// Mitsubishi GX Works2 project: Jyuden   PLC: Q00J
// 受電設備

PROGRAM MAIN
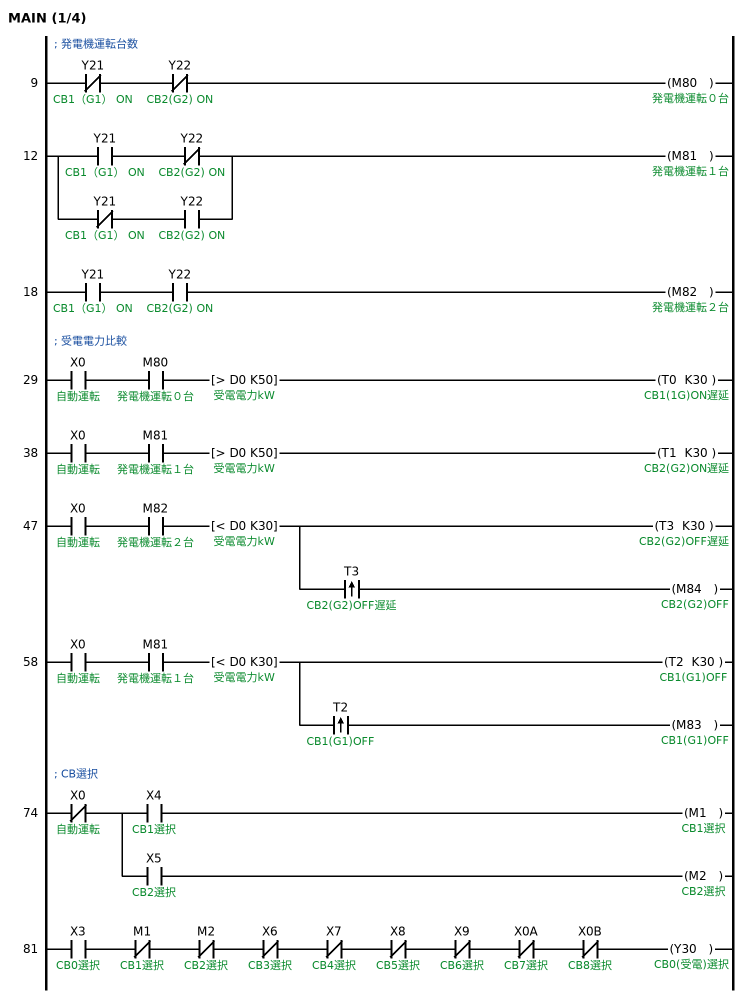
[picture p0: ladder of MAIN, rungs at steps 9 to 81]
; 発電機運転台数
9     LDI     Y21  ; CB1（G1） ON
      ANI     Y22  ; CB2(G2) ON
      OUT     M80  ; 発電機運転０台
12    LD      Y21  ; CB1（G1） ON
      ANI     Y22  ; CB2(G2) ON
      LDI     Y21  ; CB1（G1） ON
      AND     Y22  ; CB2(G2) ON
      ORB
      OUT     M81  ; 発電機運転１台
18    LD      Y21  ; CB1（G1） ON
      AND     Y22  ; CB2(G2) ON
      OUT     M82  ; 発電機運転２台
; 受電電力比較
29    LD      X0  ; 自動運転
      AND     M80  ; 発電機運転０台
      AND>    D0 K50  ; 受電電力kW
      OUT     T0 K30  ; CB1(1G)ON遅延
38    LD      X0  ; 自動運転
      AND     M81  ; 発電機運転１台
      AND>    D0 K50  ; 受電電力kW
      OUT     T1 K30  ; CB2(G2)ON遅延
47    LD      X0  ; 自動運転
      AND     M82  ; 発電機運転２台
      AND<    D0 K30  ; 受電電力kW
      OUT     T3 K30  ; CB2(G2)OFF遅延
      ANDP    T3  ; CB2(G2)OFF遅延
      OUT     M84  ; CB2(G2)OFF
58    LD      X0  ; 自動運転
      AND     M81  ; 発電機運転１台
      AND<    D0 K30  ; 受電電力kW
      OUT     T2 K30  ; CB1(G1)OFF
      ANDP    T2  ; CB1(G1)OFF
      OUT     M83  ; CB1(G1)OFF
; CB選択
74    LDI     X0  ; 自動運転
      MPS
      AND     X4  ; CB1選択
      OUT     M1  ; CB1選択
      MPP
      AND     X5  ; CB2選択
      OUT     M2  ; CB2選択
81    LD      X3  ; CB0選択
      ANI     M1  ; CB1選択
      ANI     M2  ; CB2選択
      ANI     X6  ; CB3選択
      ANI     X7  ; CB4選択
      ANI     X8  ; CB5選択
      ANI     X9  ; CB6選択
      ANI     X0A  ; CB7選択
      ANI     X0B  ; CB8選択
      OUT     Y30  ; CB0(受電)選択
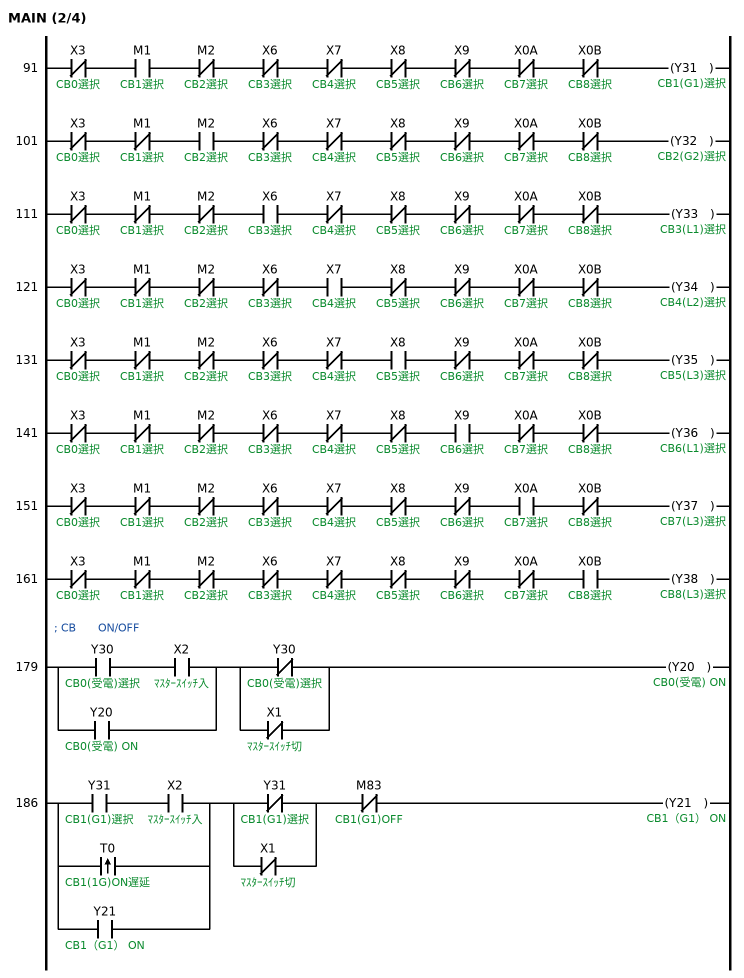
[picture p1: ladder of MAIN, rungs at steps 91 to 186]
91    LDI     X3  ; CB0選択
      AND     M1  ; CB1選択
      ANI     M2  ; CB2選択
      ANI     X6  ; CB3選択
      ANI     X7  ; CB4選択
      ANI     X8  ; CB5選択
      ANI     X9  ; CB6選択
      ANI     X0A  ; CB7選択
      ANI     X0B  ; CB8選択
      OUT     Y31  ; CB1(G1)選択
101   LDI     X3  ; CB0選択
      ANI     M1  ; CB1選択
      AND     M2  ; CB2選択
      ANI     X6  ; CB3選択
      ANI     X7  ; CB4選択
      ANI     X8  ; CB5選択
      ANI     X9  ; CB6選択
      ANI     X0A  ; CB7選択
      ANI     X0B  ; CB8選択
      OUT     Y32  ; CB2(G2)選択
111   LDI     X3  ; CB0選択
      ANI     M1  ; CB1選択
      ANI     M2  ; CB2選択
      AND     X6  ; CB3選択
      ANI     X7  ; CB4選択
      ANI     X8  ; CB5選択
      ANI     X9  ; CB6選択
      ANI     X0A  ; CB7選択
      ANI     X0B  ; CB8選択
      OUT     Y33  ; CB3(L1)選択
121   LDI     X3  ; CB0選択
      ANI     M1  ; CB1選択
      ANI     M2  ; CB2選択
      ANI     X6  ; CB3選択
      AND     X7  ; CB4選択
      ANI     X8  ; CB5選択
      ANI     X9  ; CB6選択
      ANI     X0A  ; CB7選択
      ANI     X0B  ; CB8選択
      OUT     Y34  ; CB4(L2)選択
131   LDI     X3  ; CB0選択
      ANI     M1  ; CB1選択
      ANI     M2  ; CB2選択
      ANI     X6  ; CB3選択
      ANI     X7  ; CB4選択
      AND     X8  ; CB5選択
      ANI     X9  ; CB6選択
      ANI     X0A  ; CB7選択
      ANI     X0B  ; CB8選択
      OUT     Y35  ; CB5(L3)選択
141   LDI     X3  ; CB0選択
      ANI     M1  ; CB1選択
      ANI     M2  ; CB2選択
      ANI     X6  ; CB3選択
      ANI     X7  ; CB4選択
      ANI     X8  ; CB5選択
      AND     X9  ; CB6選択
      ANI     X0A  ; CB7選択
      ANI     X0B  ; CB8選択
      OUT     Y36  ; CB6(L1)選択
151   LDI     X3  ; CB0選択
      ANI     M1  ; CB1選択
      ANI     M2  ; CB2選択
      ANI     X6  ; CB3選択
      ANI     X7  ; CB4選択
      ANI     X8  ; CB5選択
      ANI     X9  ; CB6選択
      AND     X0A  ; CB7選択
      ANI     X0B  ; CB8選択
      OUT     Y37  ; CB7(L3)選択
161   LDI     X3  ; CB0選択
      ANI     M1  ; CB1選択
      ANI     M2  ; CB2選択
      ANI     X6  ; CB3選択
      ANI     X7  ; CB4選択
      ANI     X8  ; CB5選択
      ANI     X9  ; CB6選択
      ANI     X0A  ; CB7選択
      AND     X0B  ; CB8選択
      OUT     Y38  ; CB8(L3)選択
; CB　　ON/OFF
179   LD      Y30  ; CB0(受電)選択
      AND     X2  ; ﾏｽﾀｰｽｲｯﾁ入
      OR      Y20  ; CB0(受電) ON
      LDI     Y30  ; CB0(受電)選択
      ORI     X1  ; ﾏｽﾀｰｽｲｯﾁ切
      ANB
      OUT     Y20  ; CB0(受電) ON
186   LD      Y31  ; CB1(G1)選択
      AND     X2  ; ﾏｽﾀｰｽｲｯﾁ入
      ORP     T0  ; CB1(1G)ON遅延
      OR      Y21  ; CB1（G1） ON
      LDI     Y31  ; CB1(G1)選択
      ORI     X1  ; ﾏｽﾀｰｽｲｯﾁ切
      ANB
      ANI     M83  ; CB1(G1)OFF
      OUT     Y21  ; CB1（G1） ON
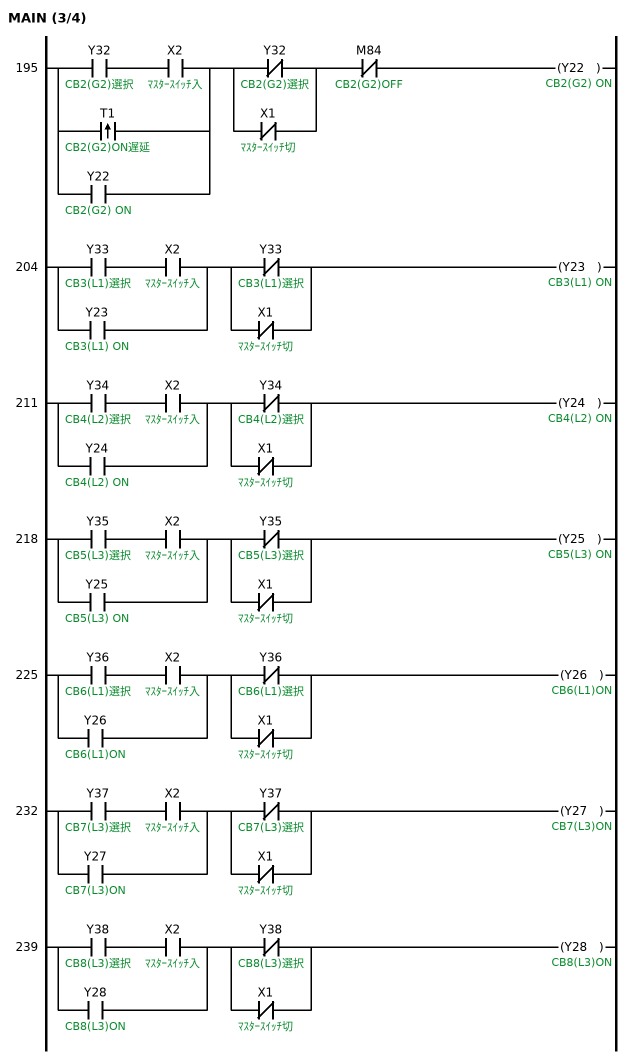
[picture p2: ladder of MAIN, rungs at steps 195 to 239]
195   LD      Y32  ; CB2(G2)選択
      AND     X2  ; ﾏｽﾀｰｽｲｯﾁ入
      ORP     T1  ; CB2(G2)ON遅延
      OR      Y22  ; CB2(G2) ON
      LDI     Y32  ; CB2(G2)選択
      ORI     X1  ; ﾏｽﾀｰｽｲｯﾁ切
      ANB
      ANI     M84  ; CB2(G2)OFF
      OUT     Y22  ; CB2(G2) ON
204   LD      Y33  ; CB3(L1)選択
      AND     X2  ; ﾏｽﾀｰｽｲｯﾁ入
      OR      Y23  ; CB3(L1) ON
      LDI     Y33  ; CB3(L1)選択
      ORI     X1  ; ﾏｽﾀｰｽｲｯﾁ切
      ANB
      OUT     Y23  ; CB3(L1) ON
211   LD      Y34  ; CB4(L2)選択
      AND     X2  ; ﾏｽﾀｰｽｲｯﾁ入
      OR      Y24  ; CB4(L2) ON
      LDI     Y34  ; CB4(L2)選択
      ORI     X1  ; ﾏｽﾀｰｽｲｯﾁ切
      ANB
      OUT     Y24  ; CB4(L2) ON
218   LD      Y35  ; CB5(L3)選択
      AND     X2  ; ﾏｽﾀｰｽｲｯﾁ入
      OR      Y25  ; CB5(L3) ON
      LDI     Y35  ; CB5(L3)選択
      ORI     X1  ; ﾏｽﾀｰｽｲｯﾁ切
      ANB
      OUT     Y25  ; CB5(L3) ON
225   LD      Y36  ; CB6(L1)選択
      AND     X2  ; ﾏｽﾀｰｽｲｯﾁ入
      OR      Y26  ; CB6(L1)ON
      LDI     Y36  ; CB6(L1)選択
      ORI     X1  ; ﾏｽﾀｰｽｲｯﾁ切
      ANB
      OUT     Y26  ; CB6(L1)ON
232   LD      Y37  ; CB7(L3)選択
      AND     X2  ; ﾏｽﾀｰｽｲｯﾁ入
      OR      Y27  ; CB7(L3)ON
      LDI     Y37  ; CB7(L3)選択
      ORI     X1  ; ﾏｽﾀｰｽｲｯﾁ切
      ANB
      OUT     Y27  ; CB7(L3)ON
239   LD      Y38  ; CB8(L3)選択
      AND     X2  ; ﾏｽﾀｰｽｲｯﾁ入
      OR      Y28  ; CB8(L3)ON
      LDI     Y38  ; CB8(L3)選択
      ORI     X1  ; ﾏｽﾀｰｽｲｯﾁ切
      ANB
      OUT     Y28  ; CB8(L3)ON
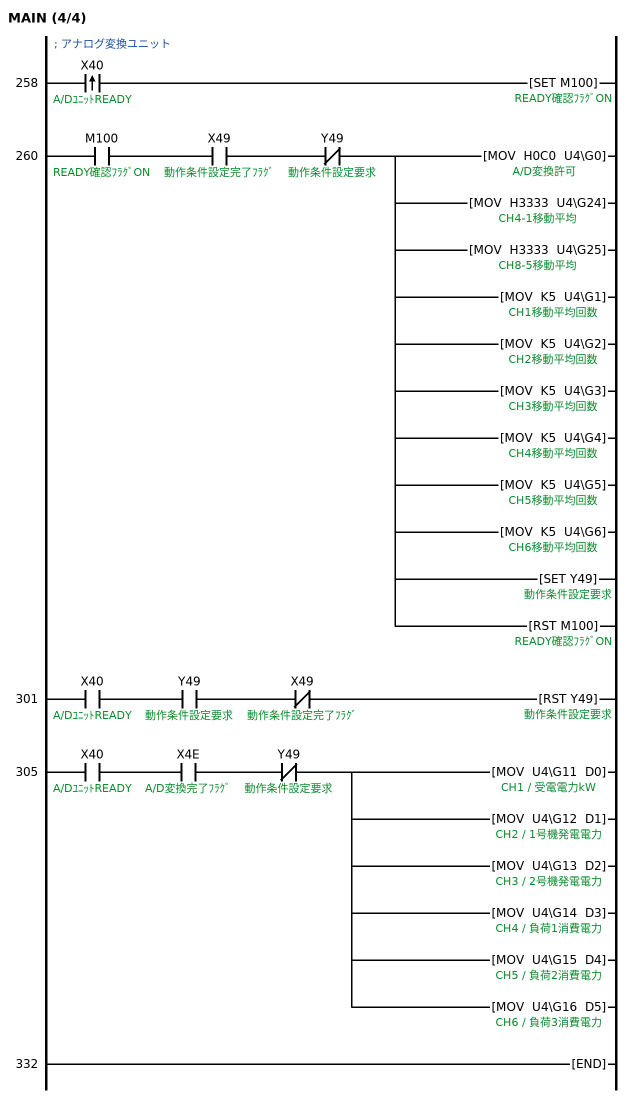
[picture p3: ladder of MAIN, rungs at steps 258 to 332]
; アナログ変換ユニット
258   LDP     X40  ; A/DﾕﾆｯﾄREADY
      SET     M100  ; READY確認ﾌﾗｸﾞON
260   LD      M100  ; READY確認ﾌﾗｸﾞON
      AND     X49  ; 動作条件設定完了ﾌﾗｸﾞ
      ANI     Y49  ; 動作条件設定要求
      MOV     H0C0 U4\G0  ; A/D変換許可
      MOV     H3333 U4\G24  ; CH4-1移動平均
      MOV     H3333 U4\G25  ; CH8-5移動平均
      MOV     K5 U4\G1  ; CH1移動平均回数
      MOV     K5 U4\G2  ; CH2移動平均回数
      MOV     K5 U4\G3  ; CH3移動平均回数
      MOV     K5 U4\G4  ; CH4移動平均回数
      MOV     K5 U4\G5  ; CH5移動平均回数
      MOV     K5 U4\G6  ; CH6移動平均回数
      SET     Y49  ; 動作条件設定要求
      RST     M100  ; READY確認ﾌﾗｸﾞON
301   LD      X40  ; A/DﾕﾆｯﾄREADY
      AND     Y49  ; 動作条件設定要求
      ANI     X49  ; 動作条件設定完了ﾌﾗｸﾞ
      RST     Y49  ; 動作条件設定要求
305   LD      X40  ; A/DﾕﾆｯﾄREADY
      AND     X4E  ; A/D変換完了ﾌﾗｸﾞ
      ANI     Y49  ; 動作条件設定要求
      MOV     U4\G11 D0  ; CH1
      MOV     U4\G12 D1  ; CH2 / 1号機発電電力
      MOV     U4\G13 D2  ; CH3 / 2号機発電電力
      MOV     U4\G14 D3  ; CH4 / 負荷1消費電力
      MOV     U4\G15 D4  ; CH5 / 負荷2消費電力
      MOV     U4\G16 D5  ; CH6 / 負荷3消費電力
332   END
END_PROGRAM
